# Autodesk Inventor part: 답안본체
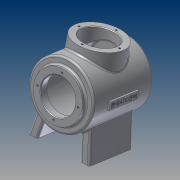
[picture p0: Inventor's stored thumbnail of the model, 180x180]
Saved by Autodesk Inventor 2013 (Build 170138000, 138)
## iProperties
Created: 2015-01
Part Number: 답안본체
Material: 알루미늄 6061
Document SubType Name: Modeling
Designer: Administrator
Mass: 1021.13 g
Surface Area: 1060.37 cm^2
Volume: 376.8 cm^3
Density: 2.71 g/cm^3
Author: Administrator
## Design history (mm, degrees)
sketch "스케치1"
  geometry: C1 r 50 at (0, 0); 1 further point
  constraints: 1 centre point, 1 coincident
  dimensions: "d0" = 100 diameter of C1
extrude "돌출1" new body sketch "스케치1" stored distance "d1" = 112; taper "d2" = 0 deg
node "작업 평면1"
sketch "스케치2"
  geometry: C1 r 38 at (0, 0); 1 further point
  constraints: 1 centre point, 1 coincident
  dimensions: "d4" = 76 diameter of C1
extrude "돌출2" join sketch "스케치2" stored distance "d5" = 112; taper "d6" = 0 deg
node "작업 평면2"
sketch "스케치3"
  geometry: C1 r 38 at (0, 0); 1 further point
  constraints: 1 centre point, 1 coincident
  dimensions: "d8" = 76 diameter of C1
extrude "돌출3" join sketch "스케치3" stored distance "d9" = 112; taper "d10" = 0 deg
node "작업 평면3"
sketch "스케치4"
  geometry: C1 r 38 at (0, 0); 1 further point
  constraints: 1 centre point, 1 coincident
  dimensions: "d12" = 76 diameter of C1
extrude "돌출4" join sketch "스케치4" stored distance "d13" = 112; taper "d14" = 0 deg
sketch "스케치5"
  geometry: C1 r 38 at (0, 0) reference; C2 r 27 at (0, 0)
  constraints: 1 centre point, 1 coincident
  dimensions: "d15" = 54 diameter of C2
extrude "돌출5" cut sketch "스케치5" distance "d16" = 189; taper "d17" = 0 deg
sketch "스케치8"
  geometry: L1 (0, 50)-(0, -47); L2 (-38, 62)-(38, 62) reference; L3 (-38, -60)-(38, -60) reference; L4 (0, 50)-(45, 50); L5 (45, 50)-(45, -47); L6 (45, -47)-(0, -47); L7 (27, -60)-(27, 62) reference; L8 (27, 50)-(27, -47); 2 further points
  constraints: 10 end point, 5 point on line, 2 perpendicular, 1 coincident, 1 parallel, 1 vertical
  dimensions: "d21" = 12 distance between parallel lines of L4 L2; "d22" = 13 distance between parallel lines of L3 L6; "d23" = 90 diameter of L5 L1
revolve "회전1" sketch "스케치8" stored, may be unused: angle "d24" = 90 deg
sketch "스케치10"
  geometry: C1 r 38 at (0, 0) reference; C2 r 27 at (0, 0)
  constraints: 1 centre point, 1 coincident
  dimensions: "d25" = 54 diameter of C2
extrude "돌출7" cut sketch "스케치10" distance "d26" = 65.5; taper "d27" = 0 deg
sketch "스케치11"
  geometry: L1 (-48, -80)-(48, -80); L2 (-48, -80)-(-39.336, -30.865); L3 (-34, -80)-(-27.282, -41.901); A1 r 50 centre (0, 0) between (-39.336, -30.865) and (-27.282, -41.901) reference; 2 further points
  constraints: 6 end point, 2 point on circle, 1 horizontal, 1 midpoint, 1 point on line, 1 vertical alignment
  dimensions: "d28" = 80 distance from line of point (0, 0) L1; "d29" = 96 distance of L1.start L1.end; "d31" = 100 deg angle of L2 L1; "d32" = 80 deg angle of L3 L1; "d33" = 14 distance of L3.start L1.start
extrude "돌출8" join sketch "스케치11" stored distance "d34" = 80; taper "d35" = 0 deg
sketch "스케치12"
  geometry: C1 r 27 at (0, 0) reference; 1 further point
  dimensions: "d36" = 32 distance of point (0, 32) C1.centre
hole "구멍1" sketch "스케치12" at (0, 32) diameter "d37" = 3.242; stored, may be unused: countersink angle "d41" = 90 deg, drill point angle "d43" = 118 deg; dims "d38" = 8, "d39" = 4, "d40" = 2, "d42" = 10
sketch "스케치13"
  geometry: C1 r 27 at (0, 0) reference; 1 further point
  dimensions: "d47" = 32 distance of point (0, 32) C1.centre
hole "구멍2" sketch "스케치13" at (0, 32) diameter "d48" = 3.242; stored, may be unused: countersink angle "d52" = 90 deg, drill point angle "d54" = 118 deg; dims "d49" = 8, "d50" = 4, "d51" = 2, "d53" = 10
sketch "스케치14"
  geometry: C1 r 27 at (0, 0) reference; 1 further point
  dimensions: "d58" = 32 distance of point (0, 32) C1.centre
hole "구멍3" sketch "스케치14" at (0, 32) diameter "d59" = 3.242; stored, may be unused: countersink angle "d63" = 90 deg, drill point angle "d65" = 118 deg; dims "d60" = 8, "d61" = 4, "d62" = 2, "d64" = 10
chamfer "모따기1" distance "d69" = 1; stored, may be unused: second distance "d70" = 2, angle "d71" = 45 deg
node "작업 평면4"
sketch "스케치15"
  geometry: L1 (-6, 27)-(6, 27); L2 (6, 27)-(6, -27); L3 (6, -27)-(-6, -27); L4 (-6, -27)-(-6, 27); 3 further points
  constraints: 8 end point, 2 midpoint, 2 parallel, 1 horizontal, 1 horizontal alignment, 1 perpendicular, 1 vertical alignment
  dimensions: "d73" = 12 distance of L1.start L1.end; "d75" = 54 distance of L1.end L2.end
extrude "돌출9" join sketch "스케치15" stored distance "d76" = 80; taper "d77" = 0 deg
sketch "스케치16"
  geometry: 2 further points
  constraints: 1 coincident, 1 other
feature "엠보싱1" sketch "스케치16" dims "d2" = 0, "d78" = 0.5, "d79" = 0
chamfer "모따기2" distance "d80" = 1; stored, may be unused: second distance "d81" = 2, angle "d82" = 45 deg
fillet "모깎기1" dims "d83" = 3
fillet "모깎기2" dims "d84" = 3
node "솔리드1"
mirror "대칭1"
pattern_circular "원형 패턴1" dims angle "d45" = 360 deg
pattern_circular "원형 패턴2" dims angle "d56" = 360 deg
pattern_circular "원형 패턴3" dims angle "d67" = 360 deg
other parameters: "d3" = 62, "d11" = 62, "d72" = 52
